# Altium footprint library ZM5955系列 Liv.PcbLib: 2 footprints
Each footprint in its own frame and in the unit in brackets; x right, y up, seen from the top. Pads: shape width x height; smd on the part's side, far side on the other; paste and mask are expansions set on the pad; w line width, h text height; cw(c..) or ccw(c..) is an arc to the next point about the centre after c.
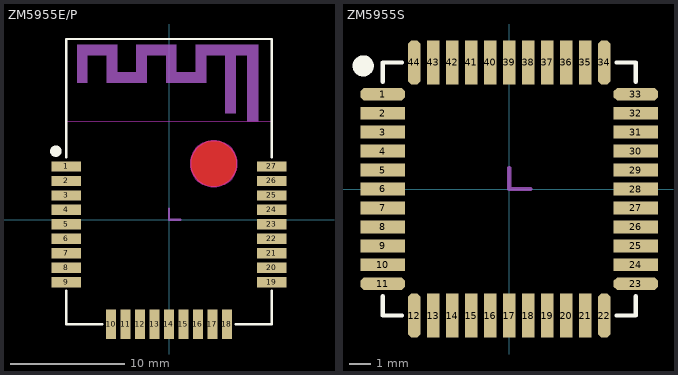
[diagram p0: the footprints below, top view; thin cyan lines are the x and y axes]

## ZM5955E/P [mm]
height 2.62
pads (27):
  rect 2.6x0.9 smd: 1(-9,4.688) 2(-9,3.418) 3(-9,2.148) 4(-9,0.878) 5(-9,-0.392) 6(-9,-1.662) 7(-9,-2.932) 8(-9,-4.202) 9(-9,-5.472) 19(9,-5.472) 20(9,-4.202) 21(9,-2.932) 22(9,-1.662) 23(9,-0.392) 24(9,0.878) 25(9,2.148) 26(9,3.418) 27(9,4.688)
  rect 0.9x2.6 smd: 10(-5.08,-9.142) 11(-3.81,-9.142) 12(-2.54,-9.142) 13(-1.27,-9.142) 14(0,-9.142) 15(1.27,-9.142) 16(2.54,-9.142) 17(3.81,-9.142) 18(5.08,-9.142)
Top Layer:
  pour cut-out: 1.892,4.924 1.892,4.724 1.97,4.331 2.123,3.962 2.345,3.63 2.628,3.347 2.96,3.125 3.33,2.972 3.722,2.894 3.922,2.894 4.122,2.894 4.514,2.972 4.883,3.125 5.216,3.347 5.499,3.63 5.721,3.962 5.874,4.331 5.952,4.724 5.952,4.924 5.952,5.124 5.874,5.516 5.721,5.885 5.499,6.218 5.216,6.5 4.883,6.723 4.514,6.876 4.122,6.954 3.922,6.954 3.722,6.954 3.33,6.876 2.96,6.723 2.628,6.5 2.345,6.218 2.123,5.885 1.97,5.516 1.892,5.124
Top Layer keep-out:
  circle w0.127: c3.922,4.924 r2.03
Top Overlay:
  circle w0.5: c-9.925,6.025 r0.25
  lines w0.2: -9,-6.221 -9,-9.142 -5.825,-9.142 ; -9,5.463 -9,15.858 9,15.858 9,5.463 ; 5.825,-9.142 9,-9.142 9,-6.221
Keep-Out Layer:
  lines w0.025: -9,8.658 9,8.658 9,15.858 -9,15.858 -9,8.658
Mechanical 15:
  circle w0.838: c3.922,4.924 r1.46
  region: -8.055,12.04 -8.055,15.34 -4.555,15.34 -4.555,12.94 -2.855,12.94 -2.855,15.34 0.645,15.34 0.645,12.94 2.345,12.94 2.345,15.34 7.845,15.34 7.845,8.642 6.845,8.642 6.845,14.44 5.845,14.44 5.845,9.365 4.945,9.365 4.945,14.44 3.245,14.44 3.245,12.04 -0.255,12.04 -0.255,14.44 -1.955,14.44 -1.955,12.04 -5.455,12.04 -5.455,14.44 -7.155,14.44 -7.155,12.04
  lines w0.2: 0,1 0,0 1,0
Multi-Layer:
  pour cut-out: -9,8.658 9,8.658 9,15.858 -9,15.858

## ZM5955S [mm]
pads (44):
  oct 2.1x0.6 smd: 1(-6,4.5) 11(-6,-4.5) 23(6,-4.5) 33(6,4.5)
  rect 2.1x0.6 smd: 2(-6,3.6) 3(-6,2.7) 4(-6,1.8) 5(-6,0.9) 6(-6,0) 7(-6,-0.9) 8(-6,-1.8) 9(-6,-2.7) 10(-6,-3.6) 24(6,-3.6) 25(6,-2.7) 26(6,-1.8) 27(6,-0.9) 28(6,0) 29(6,0.9) 30(6,1.8) 31(6,2.7) 32(6,3.6)
  oct 0.6x2.1 smd: 12(-4.5,-6) 22(4.5,-6) 34(4.5,6) 44(-4.5,6)
  rect 0.6x2.1 smd: 13(-3.6,-6) 14(-2.7,-6) 15(-1.8,-6) 16(-0.9,-6) 17(0,-6) 18(0.9,-6) 19(1.8,-6) 20(2.7,-6) 21(3.6,-6) 35(3.6,6) 36(2.7,6) 37(1.8,6) 38(0.9,6) 39(0,6) 40(-0.9,6) 41(-1.8,6) 42(-2.7,6) 43(-3.6,6)
Top Overlay:
  circle w0.5: c-6.925,5.837 r0.25
  lines w0.2: -6,-5.088 -6,-6 -5.088,-6 ; -6,5.088 -6,6 -5.088,6 ; 5.088,-6 6,-6 6,-5.088 ; 5.088,6 6,6 6,5.088
Mechanical 15:
  lines w0.2: 0,1 0,0 1,0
